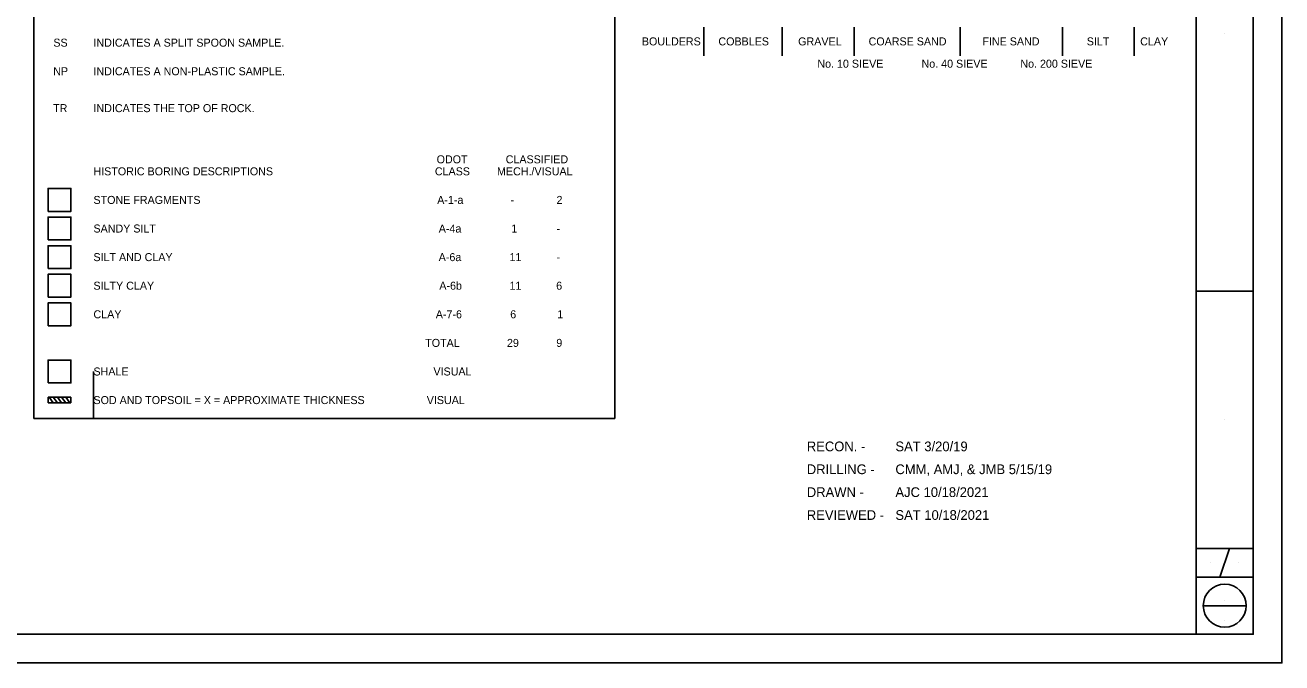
# Model space of a CAD drawing. Extents: x 0 to 34, y 0 to 22.
# Drawn here: x 12.02 to 34, y 0 to 11.15 of the extents above; entities that cross this region are included whole.
import ezdxf

# ---------------------------------------------------------------- set-up
doc = ezdxf.new("R2010")
doc.units = 0
for name, color, linetype in [('GT_Project_Soil_Layers', 7, 'Continuous'), ('SC_Scratch1', 7, 'Continuous'), ('SH_Border', 7, 'Continuous'), ('SH_Cut_Line', 7, 'Continuous'), ('SH_Data', 7, 'Continuous'), ('SH_Text', 7, 'Continuous')]:
    doc.layers.add(name, color=color, linetype=linetype)

msp = doc.modelspace()

# ---------------------------------------------------------------- linework, layer by layer
at = {"layer": 'GT_Project_Soil_Layers'}
for p, q in [((12.435, 4.645), (12.508, 4.545)), ((12.508, 4.645), (12.58, 4.545)), ((12.58, 4.645), (12.653, 4.545)), ((12.653, 4.645), (12.726, 4.545)), ((12.726, 4.645), (12.798, 4.545))]:
    msp.add_line(p, q, dxfattribs=at)
at = {"layer": 'SC_Scratch1'}
for p, q in [((13.212, 5.095), (13.212, 4.595)), ((13.212, 4.595), (13.212, 4.275))]:
    msp.add_line(p, q, dxfattribs=at)
at = {"layer": 'SH_Border'}
for p, q in [((32.5, 0.5), (32.5, 21.5)), ((32.5, 6.5), (33.5, 6.5)), ((32.5, 2), (33.5, 2)), ((32.917, 1.5), (33.083, 2)), ((32.5, 1.5), (33.5, 1.5))]:
    msp.add_line(p, q, dxfattribs=at)
msp.add_lwpolyline([(2, 21.5), (33.5, 21.5), (33.5, 0.5), (2, 0.5)], close=True, dxfattribs=at)
at = {"layer": 'SH_Cut_Line'}
msp.add_lwpolyline([(0, 0), (34, 0), (34, 22), (0, 22)], close=True, dxfattribs=at)
at = {"layer": 'SH_Data'}
for p, q in [((12.167, 4.275), (12.167, 21)), ((22.333, 4.275), (22.333, 21)), ((33, 11), (33, 11)), ((12.417, 4.545), (12.417, 4.645)), ((12.417, 4.645), (12.817, 4.645)), ((12.817, 4.545), (12.817, 4.645)), ((12.417, 4.545), (12.817, 4.545)), ((22.333, 4.275), (12.167, 4.275)), ((33, 4.25), (33, 4.25)), ((32.75, 1.75), (32.75, 1.75)), ((33.25, 1.75), (33.25, 1.75)), ((32.625, 1), (33.375, 1)), ((33, 1.085), (33, 1.085)), ((33, 0.745), (33, 0.745))]:
    msp.add_line(p, q, dxfattribs=at)
for points in [[(12.417, 7.895), (12.817, 7.895), (12.817, 8.295), (12.417, 8.295)], [(12.417, 7.395), (12.817, 7.395), (12.817, 7.795), (12.417, 7.795)], [(12.417, 6.895), (12.817, 6.895), (12.817, 7.295), (12.417, 7.295)], [(12.417, 6.395), (12.817, 6.395), (12.817, 6.795), (12.417, 6.795)], [(12.417, 5.895), (12.817, 5.895), (12.817, 6.295), (12.417, 6.295)], [(12.417, 4.895), (12.817, 4.895), (12.817, 5.295), (12.417, 5.295)]]:
    msp.add_lwpolyline(points, close=True, dxfattribs=at)
msp.add_circle((33, 1), 0.375, dxfattribs=at)
at = {"layer": 'SH_Text'}
for p, q in [((23.89, 10.617), (23.89, 11.117)), ((25.26, 10.617), (25.26, 11.117)), ((26.52, 10.617), (26.52, 11.117)), ((28.37, 10.617), (28.37, 11.117)), ((30.165, 10.617), (30.165, 11.117)), ((31.419, 10.617), (31.419, 11.117))]:
    msp.add_line(p, q, dxfattribs=at)

# ---------------------------------------------------------------- texts
for s, height, p in [('SS', 0.14, (12.51, 10.775)), ('INDICATES A SPLIT SPOON SAMPLE.', 0.14, (13.212, 10.775)), ('BOULDERS', 0.14, (22.805, 10.797)), ('COBBLES', 0.14, (24.144, 10.797)), ('GRAVEL', 0.14, (25.539, 10.797)), ('COARSE SAND', 0.14, (26.771, 10.797)), ('FINE SAND', 0.14, (28.762, 10.797)), ('SILT', 0.14, (30.587, 10.797)), ('CLAY', 0.14, (31.522, 10.797)), ('NP', 0.14, (12.508, 10.275)), ('INDICATES A NON-PLASTIC SAMPLE.', 0.14, (13.212, 10.275)), ('No. 10 SIEVE', 0.14, (25.875, 10.407)), ('No. 40 SIEVE', 0.14, (27.697, 10.407)), ('No. 200 SIEVE', 0.14, (29.426, 10.407)), ('TR', 0.14, (12.506, 9.63)), ('INDICATES THE TOP OF ROCK.', 0.14, (13.212, 9.63)), ('ODOT', 0.14, (19.215, 8.735)), ('CLASSIFIED', 0.14, (20.423, 8.735)), ('HISTORIC BORING DESCRIPTIONS', 0.14, (13.212, 8.525)), ('CLASS', 0.14, (19.184, 8.525)), ('MECH./VISUAL', 0.14, (20.271, 8.525)), ('STONE FRAGMENTS', 0.14, (13.212, 8.025)), ('A-1-a', 0.14, (19.225, 8.025)), ('2', 0.14, (21.312, 8.025)), ('-', 0.14, (20.508, 8.025)), ('SANDY SILT', 0.14, (13.212, 7.525)), ('A-4a', 0.14, (19.252, 7.525)), ('1', 0.14, (20.522, 7.525)), ('-', 0.14, (21.312, 7.525)), ('SILT AND CLAY', 0.14, (13.212, 7.025)), ('A-6a', 0.14, (19.251, 7.025)), ('11', 0.14, (20.489, 7.025)), ('-', 0.14, (21.312, 7.025)), ('SILTY CLAY', 0.14, (13.212, 6.525)), ('A-6b', 0.14, (19.262, 6.525)), ('11', 0.14, (20.489, 6.525)), ('6', 0.14, (21.306, 6.525)), ('CLAY', 0.14, (13.212, 6.025)), ('A-7-6', 0.14, (19.2, 6.025)), ('6', 0.14, (20.502, 6.025)), ('1', 0.14, (21.325, 6.025)), ('   TOTAL   ', 0.14, (18.859, 5.525)), ('29', 0.14, (20.445, 5.525)), ('9', 0.14, (21.308, 5.525)), ('SHALE', 0.14, (13.212, 5.025)), ('VISUAL', 0.14, (19.159, 5.025)), ('SOD AND TOPSOIL = X = APPROXIMATE THICKNESS', 0.14, (13.212, 4.525)), ('   VISUAL  ', 0.14, (18.886, 4.525)), ('RECON. -', 0.17, (25.69, 3.7)), ('SAT 3/20/19', 0.17, (27.24, 3.7)), ('DRILLING -', 0.17, (25.69, 3.3)), ('CMM, AMJ, & JMB 5/15/19 ', 0.17, (27.24, 3.3)), ('AJC 10/18/2021', 0.17, (27.24, 2.9)), ('DRAWN -', 0.17, (25.69, 2.9)), ('REVIEWED -', 0.17, (25.69, 2.5)), ('SAT 10/18/2021', 0.17, (27.24, 2.5))]:
    msp.add_text(s, height=height, dxfattribs=at).set_placement(p)

doc.saveas('drawing.dxf')
